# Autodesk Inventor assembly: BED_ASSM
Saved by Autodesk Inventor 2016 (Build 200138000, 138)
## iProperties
Created: 2016-03
Part Number: BED_ASSM
Document SubType Name: Assembly
Designer: bongo_000
Author: bongo_000
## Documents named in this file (6)
- C:\Users\bongo_000\Downloads\DLP\BED_ASSM.iam
- C:\Users\bongo_000\Downloads\DLP\BedBracket_LH.ipt
- C:\Users\bongo_000\Downloads\DLP\BedBracket_RH.ipt
- C:\Users\bongo_000\Downloads\DLP\BracePlate.ipt
- C:\Users\bongo_000\Downloads\DLP\Bed.ipt
- C:\Users\bongo_000\Downloads\DLP\M4_10.ipt
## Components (6 placed, 6 different names)
1. BedBracket_LH_1001
2. BedBracket_RH_1002
3. BracePlate_1003
4. Bed_1004
5. M4_10_1005
6. M4_10_1006
